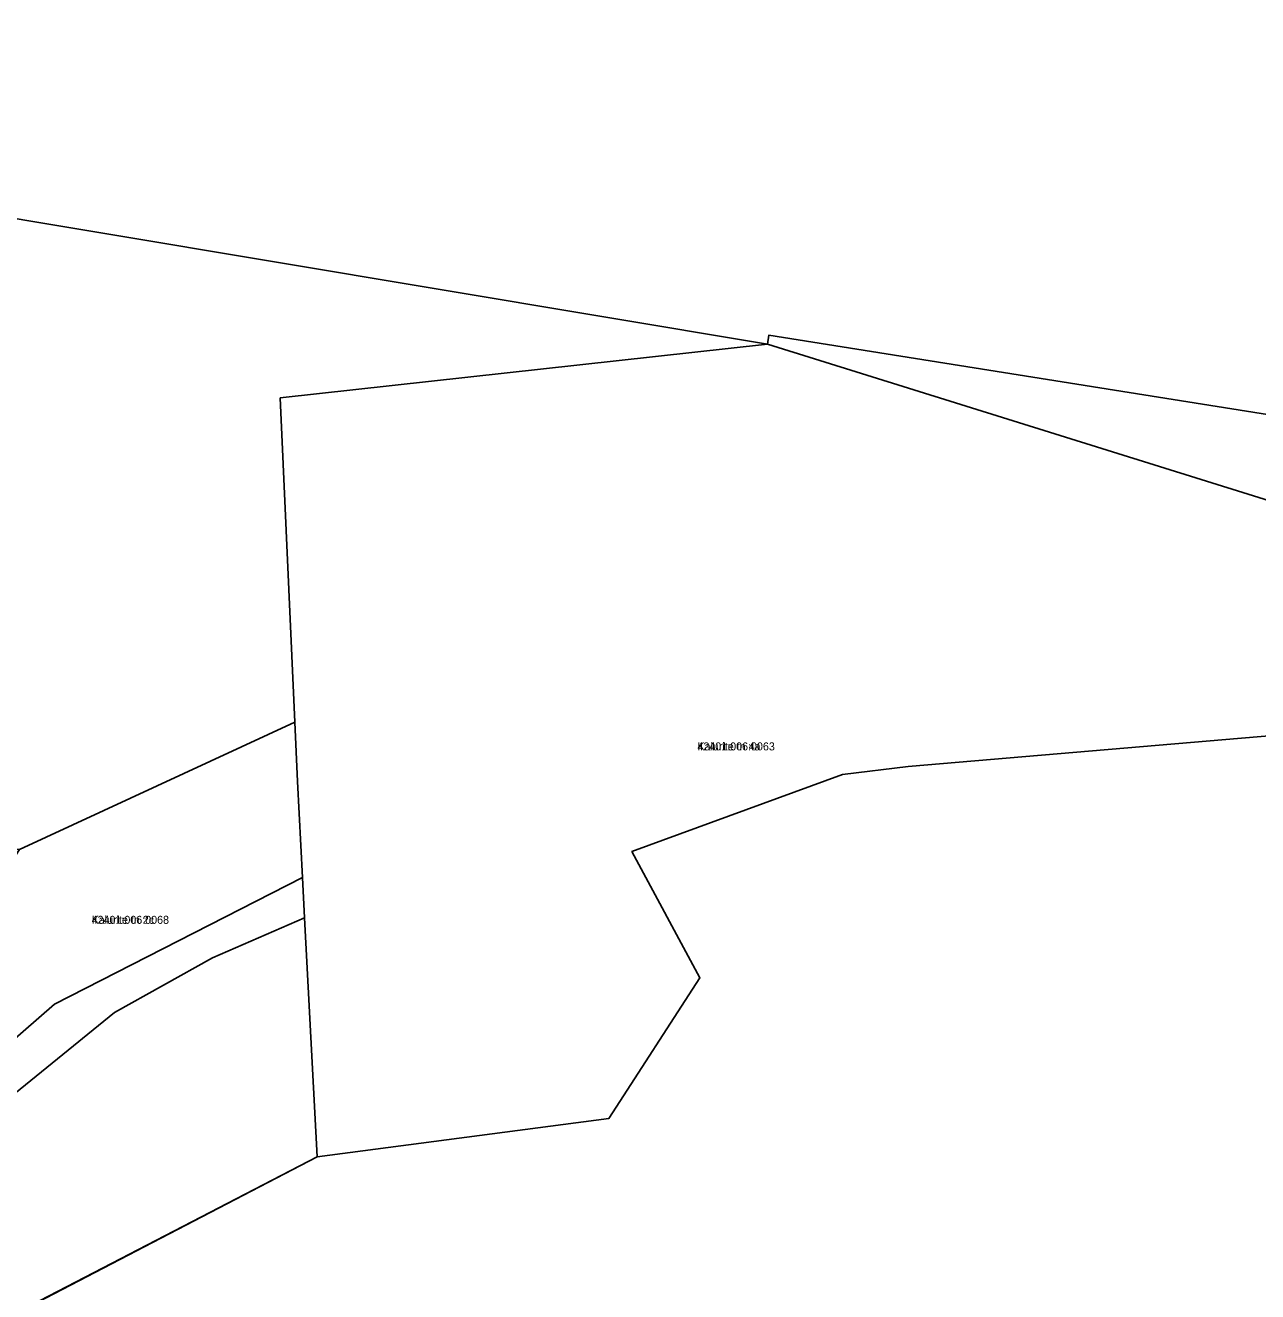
# Model space of a CAD drawing. Extents: x 595979 to 597983, y 6604231 to 6607350.
# Drawn here: x 596642.6 to 596873.6, y 6606884.7 to 6607122 of the extents above; entities that cross this region are included whole.
import ezdxf

# ---------------------------------------------------------------- set-up
doc = ezdxf.new("R2010")
doc.units = 0
for name, color, linetype in [('L_AADRESS', 7, 'Continuous'), ('PIIR', 7, 'Continuous'), ('TUNNUS', 7, 'Continuous')]:
    doc.layers.add(name, color=color, linetype=linetype)

msp = doc.modelspace()

# ---------------------------------------------------------------- linework, layer by layer
at = {"layer": 'PIIR'}
for points in [[(596564.33, 6607098.59), (596781.71, 6607062.3), (596690.42, 6607052.21), (596693.12, 6606991.47), (596641.52, 6606967.57), (596569.14, 6606969.05), (596561.08, 6607011.06), (596544.58, 6607065.45), (596541.96, 6607120.71), (596548.29, 6607122.04)], [(596697.35, 6606910.02), (596694.97, 6606954.79), (596694.59, 6606962.36), (596693.63, 6606980.36), (596693.12, 6606991.47), (596690.42, 6607052.21), (596781.71, 6607062.3), (596881.59, 6607031.12), (596883.07, 6606989.49), (596808.1, 6606983.13), (596795.77, 6606981.62), (596756.32, 6606967.19), (596769.06, 6606943.56), (596752, 6606917.18)], [(596641.52, 6606967.57), (596693.12, 6606991.47), (596693.63, 6606980.36), (596694.59, 6606962.36), (596648.1, 6606938.58), (596624.57, 6606918.1), (596608.07, 6606915.86)], [(596548.26, 6606890.04), (596464.47, 6606887.4), (596471.1, 6606905.17), (596471.94, 6606905.07), (596513.82, 6606900.6), (596545.11, 6606908.01), (596564.52, 6606909.98), (596564.33, 6606907.55), (596592.79, 6606913.83), (596608.07, 6606915.86), (596624.57, 6606918.1), (596648.1, 6606938.58), (596694.59, 6606962.36), (596694.97, 6606954.79), (596677.69, 6606947.28), (596659.33, 6606937.04), (596623.21, 6606907.76), (596558.1, 6606891.54), (596552.73, 6606890.18)], [(596552.73, 6606890.18), (596558.1, 6606891.54), (596623.21, 6606907.76), (596659.33, 6606937.04), (596677.69, 6606947.28), (596694.97, 6606954.79), (596697.35, 6606910.02), (596631, 6606875.52), (596634.38, 6606847.12), (596631.03, 6606832.78), (596620.92, 6606827.47), (596596.63, 6606830.4)]]:
    msp.add_lwpolyline(points, close=True, dxfattribs=at)
for points in [[(596881.59, 6607031.12), (596781.71, 6607062.3), (596781.96, 6607063.97), (597021.47, 6607025.87)], [(596643.75, 6606882.19), (596697.35, 6606910.02), (596752, 6606917.18), (596769.06, 6606943.56), (596756.32, 6606967.19), (596795.77, 6606981.62), (596808.1, 6606983.13), (596883.07, 6606989.49)]]:
    msp.add_lwpolyline(points, dxfattribs=at)

# ---------------------------------------------------------------- texts
at = {"layer": 'L_AADRESS'}
for s, p in [('Kalurite tn 4a', (596768.59, 6606986.16)), ('Kalurite tn 2c', (596655.06, 6606953.66))]:
    msp.add_text(s, height=1.5, dxfattribs=at).set_placement(p)
at = {"layer": 'TUNNUS'}
for s, p in [('42401:006:0063', (596768.59, 6606986.16)), ('42401:006:0068', (596655.06, 6606953.66))]:
    msp.add_text(s, height=1.5, dxfattribs=at).set_placement(p)

doc.saveas('drawing.dxf')
